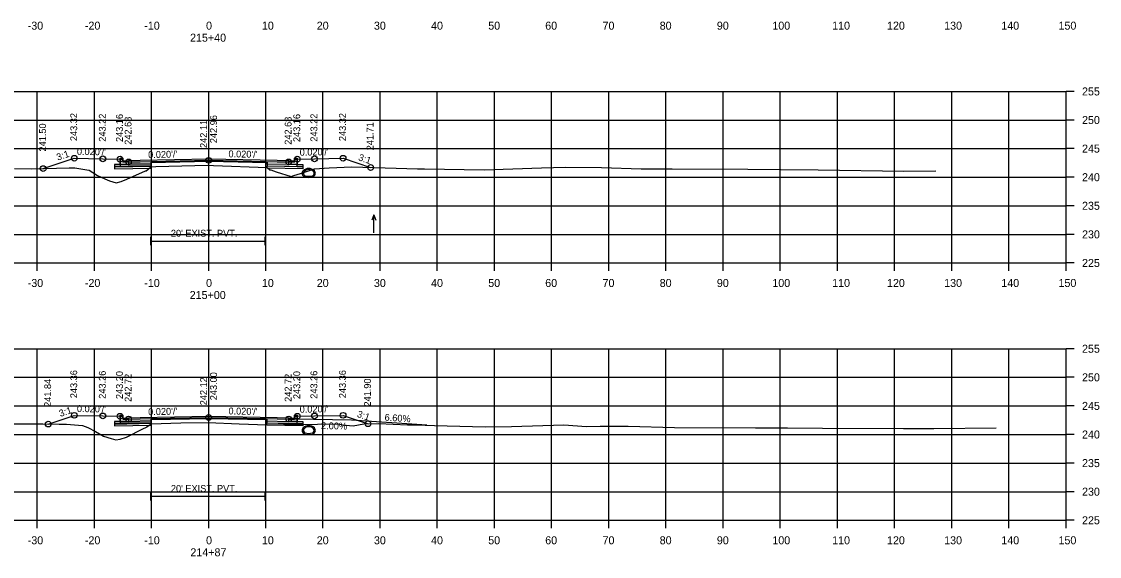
# Model space of a CAD drawing. Extents: x 1369627 to 1374022, y 380035 to 398173.
# Drawn here: x 1371506.1 to 1371694.7, y 383469.8 to 383563.4 of the extents above; entities that cross this region are included whole.
import ezdxf

# ---------------------------------------------------------------- set-up
doc = ezdxf.new("R2010")
doc.units = 0
for name, color, linetype in [('Default', 7, 'Continuous'), ('R_Alt Surface', 7, 'Continuous'), ('R_Axis', 7, 'Continuous'), ('R_Axis Annot', 7, 'Continuous'), ('R_Drive', 7, 'Continuous'), ('R_Exist Surface', 7, 'Continuous'), ('R_Fin Surface', 7, 'Continuous'), ('R_Grid', 7, 'Continuous'), ('R_No Plot', 7, 'Continuous'), ('R_Water Annot', 7, 'Continuous'), ('R_Xsect Elev', 7, 'Continuous'), ('R_Xsect Slope', 7, 'Continuous')]:
    doc.layers.add(name, color=color, linetype=linetype)

msp = doc.modelspace()

# ---------------------------------------------------------------- linework, layer by layer
at = {"layer": 'Default'}
for p, q in [((1371528.74, 383524.26), (1371528.74, 383525.76)), ((1371548.74, 383524.26), (1371548.74, 383525.76)), ((1371528.74, 383525.01), (1371548.74, 383525.01)), ((1371528.74, 383479.63), (1371528.74, 383481.13)), ((1371528.74, 383480.38), (1371548.74, 383480.38)), ((1371548.74, 383479.63), (1371548.74, 383481.13))]:
    msp.add_line(p, q, dxfattribs=at)
for points in [[(1371523.34, 383539.51), (1371523.84, 383539.51), (1371523.85, 383539.01), (1371524.85, 383539.03), (1371524.85, 383538.44), (1371523.35, 383538.41)], [(1371553.85, 383539.01), (1371553.86, 383539.51), (1371554.36, 383539.51), (1371554.35, 383538.41), (1371552.85, 383538.44), (1371552.85, 383539.03)], [(1371523.34, 383494.53), (1371523.84, 383494.53), (1371523.85, 383494.03), (1371524.85, 383494.05), (1371524.85, 383493.47), (1371523.35, 383493.44)], [(1371553.85, 383494.03), (1371553.86, 383494.53), (1371554.36, 383494.53), (1371554.35, 383493.44), (1371552.85, 383493.47), (1371552.85, 383494.05)]]:
    msp.add_lwpolyline(points, close=True, dxfattribs=at)
at = {"layer": 'R_Alt Surface'}
for points in [[(1371528.85, 383538.52), (1371524.85, 383538.44), (1371523.35, 383538.41), (1371522.35, 383538.39), (1371522.35, 383537.98), (1371528.85, 383538.11)], [(1371538.85, 383539.31), (1371526.85, 383539.07), (1371524.85, 383539.03), (1371524.85, 383538.44), (1371528.85, 383538.52), (1371528.85, 383538.94), (1371538.85, 383539.14), (1371548.85, 383538.94), (1371548.85, 383538.52), (1371552.85, 383538.44), (1371552.85, 383539.03), (1371550.85, 383539.07)], [(1371548.85, 383538.52), (1371552.85, 383538.44), (1371554.35, 383538.41), (1371555.35, 383538.39), (1371555.35, 383537.98), (1371548.85, 383538.11)], [(1371528.77, 383538.17), (1371524.85, 383538.09), (1371523.35, 383538.06), (1371522.35, 383538.04), (1371522.35, 383537.62), (1371528.77, 383537.75)], [(1371549.06, 383538.17), (1371552.85, 383538.09), (1371554.35, 383538.06), (1371555.35, 383538.04), (1371555.35, 383537.62), (1371549.06, 383537.75)], [(1371528.85, 383493.55), (1371524.85, 383493.47), (1371523.35, 383493.44), (1371522.35, 383493.42), (1371522.35, 383493), (1371528.85, 383493.13)], [(1371528.78, 383493.21), (1371524.85, 383493.13), (1371523.35, 383493.1), (1371522.35, 383493.08), (1371522.35, 383492.66), (1371528.78, 383492.79)], [(1371538.85, 383494.33), (1371526.85, 383494.09), (1371524.85, 383494.05), (1371524.85, 383493.47), (1371528.85, 383493.55), (1371528.85, 383493.96), (1371538.85, 383494.16), (1371548.85, 383493.96), (1371548.85, 383493.55), (1371552.85, 383493.47), (1371552.85, 383494.05), (1371550.85, 383494.09)], [(1371548.85, 383493.55), (1371552.85, 383493.47), (1371554.35, 383493.44), (1371555.35, 383493.42), (1371555.35, 383493), (1371548.85, 383493.13)], [(1371549.03, 383493.21), (1371552.85, 383493.13), (1371554.35, 383493.1), (1371555.35, 383493.08), (1371555.35, 383492.66), (1371549.03, 383492.79)]]:
    msp.add_lwpolyline(points, close=True, dxfattribs=at)
for points in [[(1371523.34, 383539.51), (1371523.35, 383538.41), (1371524.85, 383538.44), (1371528.85, 383538.52), (1371528.85, 383538.94), (1371538.85, 383539.14), (1371548.85, 383538.94), (1371548.85, 383538.52), (1371552.85, 383538.44), (1371554.35, 383538.41), (1371554.36, 383539.51)], [(1371523.34, 383539.32), (1371523.35, 383538.06), (1371524.85, 383538.09), (1371528.77, 383538.17), (1371528.77, 383538.75), (1371538.85, 383538.95), (1371549.06, 383538.75), (1371549.06, 383538.17), (1371552.85, 383538.09), (1371554.35, 383538.06), (1371554.36, 383539.32)], [(1371523.34, 383494.53), (1371523.35, 383493.44), (1371524.85, 383493.47), (1371528.85, 383493.55), (1371528.85, 383493.96), (1371538.85, 383494.16), (1371548.85, 383493.96), (1371548.85, 383493.55), (1371552.85, 383493.47), (1371554.35, 383493.44), (1371554.36, 383494.53)], [(1371523.34, 383494.36), (1371523.35, 383493.1), (1371524.85, 383493.13), (1371528.78, 383493.21), (1371528.78, 383493.79), (1371538.85, 383493.99), (1371549.03, 383493.79), (1371549.03, 383493.21), (1371552.85, 383493.13), (1371554.35, 383493.1), (1371554.36, 383494.36)]]:
    msp.add_lwpolyline(points, dxfattribs=at)
at = {"layer": 'R_Axis'}
for p, q in [((1371688.85, 383521.17), (1371688.85, 383551.17)), ((1371690.25, 383551.17), (1371688.85, 383551.17)), ((1371690.25, 383546.17), (1371688.85, 383546.17)), ((1371690.25, 383541.17), (1371688.85, 383541.17)), ((1371690.25, 383536.17), (1371688.85, 383536.17)), ((1371690.25, 383531.17), (1371688.85, 383531.17)), ((1371690.25, 383526.17), (1371688.85, 383526.17)), ((1371388.85, 383521.17), (1371688.85, 383521.17)), ((1371508.85, 383519.77), (1371508.85, 383521.17)), ((1371518.85, 383519.77), (1371518.85, 383521.17)), ((1371528.85, 383519.77), (1371528.85, 383521.17)), ((1371538.85, 383519.77), (1371538.85, 383521.17)), ((1371548.85, 383519.77), (1371548.85, 383521.17)), ((1371558.85, 383519.77), (1371558.85, 383521.17)), ((1371568.85, 383519.77), (1371568.85, 383521.17)), ((1371578.85, 383519.77), (1371578.85, 383521.17)), ((1371588.85, 383519.77), (1371588.85, 383521.17)), ((1371598.85, 383519.77), (1371598.85, 383521.17)), ((1371608.85, 383519.77), (1371608.85, 383521.17)), ((1371618.85, 383519.77), (1371618.85, 383521.17)), ((1371628.85, 383519.77), (1371628.85, 383521.17)), ((1371638.85, 383519.77), (1371638.85, 383521.17)), ((1371648.85, 383519.77), (1371648.85, 383521.17)), ((1371658.85, 383519.77), (1371658.85, 383521.17)), ((1371668.85, 383519.77), (1371668.85, 383521.17)), ((1371678.85, 383519.77), (1371678.85, 383521.17)), ((1371688.85, 383519.77), (1371688.85, 383521.17)), ((1371690.25, 383521.17), (1371688.85, 383521.17)), ((1371688.85, 383476.17), (1371688.85, 383506.17)), ((1371690.25, 383506.17), (1371688.85, 383506.17)), ((1371690.25, 383501.17), (1371688.85, 383501.17)), ((1371690.25, 383496.17), (1371688.85, 383496.17)), ((1371690.25, 383491.17), (1371688.85, 383491.17)), ((1371690.25, 383486.17), (1371688.85, 383486.17)), ((1371690.25, 383481.17), (1371688.85, 383481.17)), ((1371388.85, 383476.17), (1371688.85, 383476.17)), ((1371508.85, 383474.77), (1371508.85, 383476.17)), ((1371518.85, 383474.77), (1371518.85, 383476.17)), ((1371528.85, 383474.77), (1371528.85, 383476.17)), ((1371538.85, 383474.77), (1371538.85, 383476.17)), ((1371548.85, 383474.77), (1371548.85, 383476.17)), ((1371558.85, 383474.77), (1371558.85, 383476.17)), ((1371568.85, 383474.77), (1371568.85, 383476.17)), ((1371578.85, 383474.77), (1371578.85, 383476.17)), ((1371588.85, 383474.77), (1371588.85, 383476.17)), ((1371598.85, 383474.77), (1371598.85, 383476.17)), ((1371608.85, 383474.77), (1371608.85, 383476.17)), ((1371618.85, 383474.77), (1371618.85, 383476.17)), ((1371628.85, 383474.77), (1371628.85, 383476.17)), ((1371638.85, 383474.77), (1371638.85, 383476.17)), ((1371648.85, 383474.77), (1371648.85, 383476.17)), ((1371658.85, 383474.77), (1371658.85, 383476.17)), ((1371668.85, 383474.77), (1371668.85, 383476.17)), ((1371678.85, 383474.77), (1371678.85, 383476.17)), ((1371688.85, 383474.77), (1371688.85, 383476.17)), ((1371690.25, 383476.17), (1371688.85, 383476.17))]:
    msp.add_line(p, q, dxfattribs=at)
at = {"layer": 'R_Drive'}
for p, q in [((1371563.85, 383493.66), (1371553.85, 383493.86)), ((1371577.01, 383492.79), (1371563.85, 383493.66))]:
    msp.add_line(p, q, dxfattribs=at)
for centre, radius, start, end in [((1371555.84, 383536.85), 0.646, 136.3515, 253.9529), ((1371556.36, 383536.36), 1.35, 43.6485, 136.3515), ((1371555.84, 383536.85), 0.438, 136.3515, 253.9529), ((1371556.36, 383536.36), 1.15, 43.6485, 136.3515), ((1371556.87, 383536.85), 0.438, 286.0471, 43.6485), ((1371556.87, 383536.85), 0.646, 286.0471, 43.6485), ((1371556.36, 383538.63), 2.5, 253.9529, 286.0471), ((1371556.36, 383538.63), 2.29, 253.9529, 286.0471), ((1371555.84, 383491.88), 0.646, 136.3515, 253.9529), ((1371556.36, 383491.39), 1.35, 43.6485, 136.3515), ((1371555.84, 383491.88), 0.438, 136.3515, 253.9529), ((1371556.36, 383491.39), 1.15, 43.6485, 136.3515), ((1371556.36, 383493.66), 2.29, 253.9529, 286.0471), ((1371556.87, 383491.88), 0.438, 286.0471, 43.6485), ((1371556.87, 383491.88), 0.646, 286.0471, 43.6485), ((1371556.36, 383493.66), 2.5, 253.9529, 286.0471)]:
    msp.add_arc(centre, radius, start, end, dxfattribs=at)
at = {"layer": 'R_Exist Surface'}
for points in [[(1371504.86, 383537.68), (1371507.87, 383537.61), (1371514.42, 383537.81), (1371515.44, 383537.81), (1371517.88, 383537.38), (1371517.92, 383537.38), (1371519.38, 383536.47), (1371520.69, 383535.9), (1371521.48, 383535.55), (1371522.68, 383535.16), (1371523.51, 383535.43), (1371524.54, 383535.83), (1371527.82, 383537.26), (1371527.89, 383537.29), (1371528.68, 383537.93), (1371528.77, 383538.01), (1371529.62, 383538.03), (1371538.7, 383538.28), (1371539.72, 383538.24), (1371549.06, 383537.86), (1371549.06, 383537.86), (1371549.55, 383537.48), (1371549.71, 383537.46), (1371550.63, 383537.12), (1371553.29, 383536.32), (1371553.73, 383536.44), (1371554.91, 383536.81), (1371557.34, 383537.64), (1371559.94, 383537.78), (1371563.89, 383537.96), (1371571.66, 383537.75), (1371575.36, 383537.65), (1371576.62, 383537.61), (1371587.06, 383537.45), (1371597.07, 383537.8), (1371601.26, 383537.95), (1371607.58, 383537.87), (1371614.51, 383537.61), (1371619.92, 383537.61), (1371633.18, 383537.56), (1371638.95, 383537.5), (1371645.5, 383537.43), (1371660.45, 383537.23), (1371666.05, 383537.3)], [(1371504.81, 383493.05), (1371507.59, 383493.02), (1371509.81, 383493.01), (1371512.68, 383493), (1371513.98, 383492.99), (1371516.78, 383492.74), (1371517.71, 383492.42), (1371519.05, 383491.68), (1371520.45, 383490.89), (1371521.79, 383490.48), (1371522.6, 383490.25), (1371523.38, 383490.38), (1371524.49, 383490.72), (1371527.35, 383492.17), (1371527.95, 383492.44), (1371528.01, 383492.49), (1371528.78, 383493.06), (1371533.95, 383493.2), (1371538.75, 383493.29), (1371544.18, 383493.06), (1371549.03, 383492.89), (1371550, 383492.84), (1371551.96, 383492.92), (1371557.88, 383492.98), (1371561.57, 383493.05), (1371562.28, 383492.89), (1371564.11, 383492.69), (1371565.99, 383493.04), (1371568.63, 383493.12), (1371573.64, 383492.89), (1371575.07, 383492.85), (1371578.38, 383492.75), (1371587.22, 383492.51), (1371591.82, 383492.56), (1371600.99, 383492.86), (1371604.97, 383492.58), (1371607.34, 383492.63), (1371612.23, 383492.65), (1371620.36, 383492.4), (1371634.52, 383492.33), (1371640.14, 383492.31), (1371646.23, 383492.25), (1371660.42, 383492.21), (1371662.74, 383492.23), (1371665.74, 383492.21), (1371676.63, 383492.34)]]:
    msp.add_lwpolyline(points, dxfattribs=at)
at = {"layer": 'R_Fin Surface'}
for points in [[(1371509.89, 383537.67), (1371515.34, 383539.48), (1371520.34, 383539.38), (1371523.34, 383539.32), (1371523.84, 383539.32), (1371523.85, 383538.82), (1371524.85, 383538.84), (1371526.85, 383538.88), (1371538.85, 383539.12), (1371550.85, 383538.88), (1371552.85, 383538.84), (1371553.85, 383538.82), (1371553.86, 383539.32), (1371554.36, 383539.32), (1371557.36, 383539.38), (1371562.36, 383539.48), (1371567.19, 383537.87)], [(1371510.78, 383493), (1371515.34, 383494.52), (1371520.34, 383494.42), (1371523.34, 383494.36), (1371523.84, 383494.36), (1371523.85, 383493.86), (1371524.85, 383493.88), (1371526.85, 383493.92), (1371538.85, 383494.16), (1371550.85, 383493.92), (1371552.85, 383493.88), (1371553.85, 383493.86), (1371553.86, 383494.36), (1371554.36, 383494.36), (1371557.36, 383494.42), (1371562.36, 383494.52), (1371566.73, 383493.06)]]:
    msp.add_lwpolyline(points, dxfattribs=at)
at = {"layer": 'R_Grid'}
for p, q in [((1371388.85, 383551.17), (1371688.85, 383551.17)), ((1371508.85, 383521.17), (1371508.85, 383551.17)), ((1371518.85, 383521.17), (1371518.85, 383551.17)), ((1371528.85, 383521.17), (1371528.85, 383551.17)), ((1371538.85, 383521.17), (1371538.85, 383551.17)), ((1371548.85, 383521.17), (1371548.85, 383551.17)), ((1371558.85, 383521.17), (1371558.85, 383551.17)), ((1371568.85, 383521.17), (1371568.85, 383551.17)), ((1371578.85, 383521.17), (1371578.85, 383551.17)), ((1371588.85, 383521.17), (1371588.85, 383551.17)), ((1371598.85, 383521.17), (1371598.85, 383551.17)), ((1371608.85, 383521.17), (1371608.85, 383551.17)), ((1371618.85, 383521.17), (1371618.85, 383551.17)), ((1371628.85, 383521.17), (1371628.85, 383551.17)), ((1371638.85, 383521.17), (1371638.85, 383551.17)), ((1371648.85, 383521.17), (1371648.85, 383551.17)), ((1371658.85, 383521.17), (1371658.85, 383551.17)), ((1371668.85, 383521.17), (1371668.85, 383551.17)), ((1371678.85, 383521.17), (1371678.85, 383551.17)), ((1371688.85, 383521.17), (1371688.85, 383551.17)), ((1371388.85, 383546.17), (1371688.85, 383546.17)), ((1371388.85, 383541.17), (1371688.85, 383541.17)), ((1371388.85, 383536.17), (1371688.85, 383536.17)), ((1371388.85, 383531.17), (1371688.85, 383531.17)), ((1371388.85, 383526.17), (1371688.85, 383526.17)), ((1371388.85, 383521.17), (1371688.85, 383521.17)), ((1371388.85, 383506.17), (1371688.85, 383506.17)), ((1371508.85, 383476.17), (1371508.85, 383506.17)), ((1371518.85, 383476.17), (1371518.85, 383506.17)), ((1371528.85, 383476.17), (1371528.85, 383506.17)), ((1371538.85, 383476.17), (1371538.85, 383506.17)), ((1371548.85, 383476.17), (1371548.85, 383506.17)), ((1371558.85, 383476.17), (1371558.85, 383506.17)), ((1371568.85, 383476.17), (1371568.85, 383506.17)), ((1371578.85, 383476.17), (1371578.85, 383506.17)), ((1371588.85, 383476.17), (1371588.85, 383506.17)), ((1371598.85, 383476.17), (1371598.85, 383506.17)), ((1371608.85, 383476.17), (1371608.85, 383506.17)), ((1371618.85, 383476.17), (1371618.85, 383506.17)), ((1371628.85, 383476.17), (1371628.85, 383506.17)), ((1371638.85, 383476.17), (1371638.85, 383506.17)), ((1371648.85, 383476.17), (1371648.85, 383506.17)), ((1371658.85, 383476.17), (1371658.85, 383506.17)), ((1371668.85, 383476.17), (1371668.85, 383506.17)), ((1371678.85, 383476.17), (1371678.85, 383506.17)), ((1371688.85, 383476.17), (1371688.85, 383506.17)), ((1371388.85, 383501.17), (1371688.85, 383501.17)), ((1371388.85, 383496.17), (1371688.85, 383496.17)), ((1371388.85, 383491.17), (1371688.85, 383491.17)), ((1371388.85, 383486.17), (1371688.85, 383486.17)), ((1371388.85, 383481.17), (1371688.85, 383481.17)), ((1371388.85, 383476.17), (1371688.85, 383476.17))]:
    msp.add_line(p, q, dxfattribs=at)
at = {"layer": 'R_No Plot'}
for centre in [(1371515.34, 383539.48), (1371520.34, 383539.38), (1371523.34, 383539.32), (1371524.85, 383538.84), (1371538.85, 383539.12), (1371552.85, 383538.84), (1371554.36, 383539.32), (1371557.36, 383539.38), (1371562.36, 383539.48), (1371509.89, 383537.67), (1371567.19, 383537.87), (1371510.78, 383493), (1371515.34, 383494.52), (1371520.34, 383494.42), (1371523.34, 383494.36), (1371524.85, 383493.88), (1371538.85, 383494.16), (1371552.85, 383493.88), (1371554.36, 383494.36), (1371557.36, 383494.42), (1371562.36, 383494.52), (1371566.73, 383493.06)]:
    msp.add_circle(centre, 0.5, dxfattribs=at)
at = {"layer": 'R_Water Annot'}
for p, q in [((1371567.75, 383529.59), (1371567.4, 383528.63)), ((1371567.75, 383526.45), (1371567.75, 383529.59)), ((1371567.75, 383529.59), (1371568.1, 383528.63))]:
    msp.add_line(p, q, dxfattribs=at)
at = {"layer": 'R_Xsect Elev'}
for p, q in [((1371538.85, 383538.28), (1371538.85, 383548.28)), ((1371538.85, 383493.28), (1371538.85, 383503.28))]:
    msp.add_line(p, q, dxfattribs=at)

# ---------------------------------------------------------------- texts
at = {"layer": 'R_Axis Annot'}
for s, height, p in [('-30', 1.4, (1371507.19, 383561.97)), ('-20', 1.4, (1371517.19, 383561.97)), ('-10', 1.4, (1371527.58, 383561.97)), ('0', 1.4, (1371538.39, 383561.97)), ('10', 1.4, (1371548.16, 383561.97)), ('20', 1.4, (1371557.76, 383561.97)), ('30', 1.4, (1371567.76, 383561.97)), ('40', 1.4, (1371577.76, 383561.97)), ('50', 1.4, (1371587.76, 383561.97)), ('60', 1.4, (1371597.73, 383561.97)), ('70', 1.4, (1371607.76, 383561.97)), ('80', 1.4, (1371617.76, 383561.97)), ('90', 1.4, (1371627.76, 383561.97)), ('100', 1.4, (1371637.47, 383561.97)), ('110', 1.4, (1371647.93, 383561.97)), ('120', 1.4, (1371657.53, 383561.97)), ('130', 1.4, (1371667.53, 383561.97)), ('140', 1.4, (1371677.53, 383561.97)), ('150', 1.4, (1371687.53, 383561.97)), ('215+40', 1.4, (1371535.59, 383559.87)), ('255', 1.4, (1371691.65, 383550.47)), ('250', 1.4, (1371691.65, 383545.47)), ('245', 1.4, (1371691.65, 383540.47)), ('240', 1.4, (1371691.65, 383535.47)), ('235', 1.4, (1371691.65, 383530.47)), ("20' EXIST. PVT.", 1.2, (1371532.24, 383525.77)), ('230', 1.4, (1371691.65, 383525.47)), ('225', 1.4, (1371691.65, 383520.47)), ('-30', 1.4, (1371507.19, 383516.97)), ('-20', 1.4, (1371517.19, 383516.97)), ('-10', 1.4, (1371527.58, 383516.97)), ('0', 1.4, (1371538.39, 383516.97)), ('10', 1.4, (1371548.16, 383516.97)), ('20', 1.4, (1371557.76, 383516.97)), ('30', 1.4, (1371567.76, 383516.97)), ('40', 1.4, (1371577.76, 383516.97)), ('50', 1.4, (1371587.76, 383516.97)), ('60', 1.4, (1371597.73, 383516.97)), ('70', 1.4, (1371607.76, 383516.97)), ('80', 1.4, (1371617.76, 383516.97)), ('90', 1.4, (1371627.76, 383516.97)), ('100', 1.4, (1371637.47, 383516.97)), ('110', 1.4, (1371647.93, 383516.97)), ('120', 1.4, (1371657.53, 383516.97)), ('130', 1.4, (1371667.53, 383516.97)), ('140', 1.4, (1371677.53, 383516.97)), ('150', 1.4, (1371687.53, 383516.97)), ('215+00', 1.4, (1371535.53, 383514.87)), ('255', 1.4, (1371691.65, 383505.47)), ('250', 1.4, (1371691.65, 383500.47)), ('245', 1.4, (1371691.65, 383495.47)), ('240', 1.4, (1371691.65, 383490.47)), ('235', 1.4, (1371691.65, 383485.47)), ("20' EXIST. PVT.", 1.2, (1371532.24, 383481.13)), ('230', 1.4, (1371691.65, 383480.47)), ('225', 1.4, (1371691.65, 383475.47)), ('-30', 1.4, (1371507.19, 383471.97)), ('-20', 1.4, (1371517.19, 383471.97)), ('-10', 1.4, (1371527.58, 383471.97)), ('0', 1.4, (1371538.39, 383471.97)), ('10', 1.4, (1371548.16, 383471.97)), ('20', 1.4, (1371557.76, 383471.97)), ('30', 1.4, (1371567.76, 383471.97)), ('40', 1.4, (1371577.76, 383471.97)), ('50', 1.4, (1371587.76, 383471.97)), ('60', 1.4, (1371597.73, 383471.97)), ('70', 1.4, (1371607.76, 383471.97)), ('80', 1.4, (1371617.76, 383471.97)), ('90', 1.4, (1371627.76, 383471.97)), ('100', 1.4, (1371637.47, 383471.97)), ('110', 1.4, (1371647.93, 383471.97)), ('120', 1.4, (1371657.53, 383471.97)), ('130', 1.4, (1371667.53, 383471.97)), ('140', 1.4, (1371677.53, 383471.97)), ('150', 1.4, (1371687.53, 383471.97)), ('214+87', 1.4, (1371535.65, 383469.87))]:
    msp.add_text(s, height=height, dxfattribs=at).set_placement(p)
at = {"layer": 'R_Xsect Elev'}
for s, rotation, p in [('243.32', 90, (1371515.84, 383542.48)), ('243.22', 90, (1371520.84, 383542.38)), ('243.16', 90, (1371523.84, 383542.32)), ('242.68', 90, (1371525.35, 383541.84)), ('242.11', 90, (1371538.55, 383541.28)), ('242.96', 90, (1371540.3, 383542.12)), ('242.68', 90, (1371553.35, 383541.84)), ('243.16', 90, (1371554.86, 383542.32)), ('243.22', 90, (1371557.86, 383542.38)), ('243.32', 90, (1371562.86, 383542.48)), ('241.50', 90, (1371510.39, 383540.67)), ('241.71', 90, (1371567.69, 383540.87)), ('241.84', 90, (1371511.28, 383496)), ('243.36', 90, (1371515.84, 383497.52)), ('243.26', 90, (1371520.84, 383497.42)), ('243.20', 90, (1371523.84, 383497.36)), ('242.72', 90, (1371525.35, 383496.88)), ('242.12', 90, (1371538.55, 383496.28)), ('243.00', 90, (1371540.3, 383497.16)), ('242.72', 90, (1371553.35, 383496.88)), ('243.20', 90, (1371554.86, 383497.36)), ('243.26', 90, (1371557.86, 383497.42)), ('243.36', 90, (1371562.86, 383497.52)), ('241.90', 90, (1371567.23, 383496.06)), ('2.00%', 358.8542, (1371558.5, 383492.12)), ('6.60%', 356.224, (1371569.6, 383493.6))]:
    msp.add_text(s, height=1.2, rotation=rotation, dxfattribs=at).set_placement(p)
at = {"layer": 'R_Xsect Slope'}
for s, rotation, p in [('3:1', 18.4332, (1371512.45, 383539.05)), ("0.020'/'", 358.8542, (1371515.79, 383540.08)), ("0.020'/'", 1.1458, (1371528.27, 383539.51)), ("0.020'/'", 358.8542, (1371542.3, 383539.66)), ("0.020'/'", 1.1458, (1371554.78, 383539.93)), ('3:1', 341.5668, (1371564.93, 383539.15)), ('3:1', 18.4332, (1371512.9, 383494.24)), ("0.020'/'", 358.8542, (1371515.79, 383495.11)), ("0.020'/'", 1.1458, (1371528.27, 383494.55)), ("0.020'/'", 358.8542, (1371542.3, 383494.69)), ("0.020'/'", 1.1458, (1371554.78, 383494.97)), ('3:1', 341.5668, (1371564.7, 383494.27))]:
    msp.add_text(s, height=1.2, rotation=rotation, dxfattribs=at).set_placement(p)

doc.saveas('drawing.dxf')
